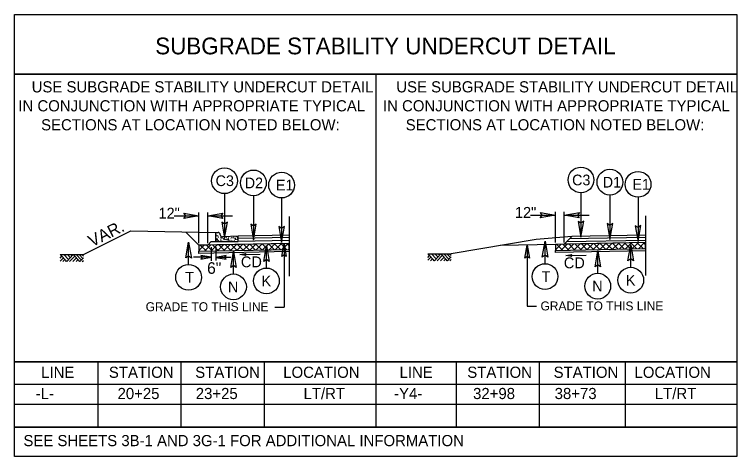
# Model space of a CAD drawing. Extents: x 1904401 to 1905163, y 193929 to 194736.
# Drawn here: x 1904819.8 to 1904900.7, y 193929.1 to 193978.6 of the extents above; entities that cross this region are included whole.
import ezdxf

# ---------------------------------------------------------------- set-up
doc = ezdxf.new("R2010")
doc.units = 0
for name, color, linetype in [('Old_Level_1', 7, 'Continuous'), ('Old_Level_11', 7, 'Continuous'), ('Old_Level_19', 7, 'Continuous'), ('Prop Lane Arrow CELL', 7, 'Continuous'), ('Prop Terminator CELL', 7, 'Continuous'), ('Typical Berm CELL', 7, 'Continuous'), ('Typical Curb CELL', 7, 'Continuous'), ('Typical Detail Wedge1 CELL', 7, 'Continuous'), ('Typical Hinge Slope Arterial CELL', 7, 'Continuous'), ('Typical ID Circle CELL', 7, 'Continuous'), ('Typical Pavement Slope CELL', 7, 'Continuous'), ('Typical Terminator CELL', 7, 'Continuous'), ('Typical Text General CELL', 7, 'Continuous'), ('Typical Text ID Circle CELL', 7, 'Continuous')]:
    doc.layers.add(name, color=color, linetype=linetype)

msp = doc.modelspace()

# ---------------------------------------------------------------- linework, layer by layer
at = {"layer": 'Old_Level_1'}
for p, q in [((1904840.413, 193952.944), (1904840.413, 193956.386)), ((1904841.413, 193952.944), (1904841.413, 193956.386)), ((1904880.325, 193953.027), (1904880.325, 193956.47)), ((1904881.325, 193953.027), (1904881.325, 193956.47)), ((1904837.638, 193956.011), (1904840.413, 193956.011)), ((1904841.413, 193956.011), (1904844.186, 193956.011)), ((1904850.507, 193955.947), (1904850.507, 193949.274)), ((1904877.55, 193956.094), (1904880.325, 193956.094)), ((1904881.325, 193956.094), (1904884.098, 193956.094)), ((1904890.419, 193956.031), (1904890.419, 193949.357)), ((1904850.507, 193953.852), (1904844.804, 193953.738)), ((1904890.419, 193953.852), (1904882.175, 193953.687)), ((1904850.507, 193953.602), (1904844.804, 193953.488)), ((1904850.507, 193953.268), (1904844.804, 193953.154)), ((1904878.175, 193953.367), (1904868.658, 193951.78)), ((1904882.175, 193953.687), (1904878.175, 193953.367)), ((1904890.419, 193953.018), (1904880.325, 193952.816)), ((1904882.175, 193953.687), (1904881.325, 193952.836)), ((1904890.419, 193953.018), (1904881.325, 193952.836)), ((1904890.419, 193953.268), (1904881.58, 193953.091)), ((1904890.419, 193953.602), (1904881.92, 193953.432)), ((1904888.181, 193952.307), (1904888.862, 193952.987)), ((1904888.795, 193952.986), (1904889.449, 193952.332)), ((1904888.903, 193952.321), (1904889.583, 193953.001)), ((1904889.488, 193953), (1904890.142, 193952.346)), ((1904889.625, 193952.335), (1904890.305, 193953.016)), ((1904890.182, 193953.013), (1904890.419, 193952.776)), ((1904890.419, 193952.351), (1904890.419, 193953.018)), ((1904850.507, 193952.935), (1904840.413, 193952.733)), ((1904841.413, 193952.753), (1904840.413, 193952.733)), ((1904840.413, 193952.145), (1904841.013, 193952.745)), ((1904840.413, 193952.733), (1904840.413, 193952.066)), ((1904840.413, 193952.066), (1904850.507, 193952.268)), ((1904840.413, 193952.18), (1904840.525, 193952.068)), ((1904840.564, 193952.736), (1904841.218, 193952.082)), ((1904841.054, 193952.079), (1904841.734, 193952.759)), ((1904841.257, 193952.75), (1904841.911, 193952.096)), ((1904850.507, 193952.935), (1904841.413, 193952.753)), ((1904841.775, 193952.093), (1904842.456, 193952.774)), ((1904841.951, 193952.764), (1904842.604, 193952.11)), ((1904842.497, 193952.108), (1904843.177, 193952.788)), ((1904842.644, 193952.778), (1904843.298, 193952.124)), ((1904843.219, 193952.122), (1904843.899, 193952.803)), ((1904843.337, 193952.791), (1904843.991, 193952.138)), ((1904843.94, 193952.137), (1904844.621, 193952.817)), ((1904844.03, 193952.805), (1904844.684, 193952.152)), ((1904844.662, 193952.151), (1904845.342, 193952.832)), ((1904844.724, 193952.819), (1904845.377, 193952.165)), ((1904845.383, 193952.166), (1904846.064, 193952.846)), ((1904845.417, 193952.833), (1904846.071, 193952.179)), ((1904846.105, 193952.18), (1904846.785, 193952.86)), ((1904846.11, 193952.847), (1904846.764, 193952.193)), ((1904846.803, 193952.861), (1904847.457, 193952.207)), ((1904846.826, 193952.194), (1904847.507, 193952.875)), ((1904847.497, 193952.875), (1904848.15, 193952.221)), ((1904847.548, 193952.209), (1904848.228, 193952.889)), ((1904848.19, 193952.888), (1904848.844, 193952.235)), ((1904848.269, 193952.223), (1904848.95, 193952.904)), ((1904848.883, 193952.902), (1904849.537, 193952.249)), ((1904848.991, 193952.238), (1904849.671, 193952.918)), ((1904849.576, 193952.916), (1904850.23, 193952.262)), ((1904849.712, 193952.252), (1904850.393, 193952.933)), ((1904849.943, 193952.924), (1904849.943, 193945.791)), ((1904850.27, 193952.93), (1904850.507, 193952.692)), ((1904850.434, 193952.267), (1904850.507, 193952.34)), ((1904850.507, 193952.268), (1904850.507, 193952.935)), ((1904880.325, 193952.816), (1904874.129, 193952.692)), ((1904877.173, 193952.753), (1904877.173, 193945.924)), ((1904881.325, 193952.836), (1904880.325, 193952.816)), ((1904880.325, 193952.228), (1904880.925, 193952.828)), ((1904880.325, 193952.816), (1904880.325, 193952.149)), ((1904880.325, 193952.149), (1904890.419, 193952.351)), ((1904880.325, 193952.263), (1904880.437, 193952.152)), ((1904880.476, 193952.819), (1904881.13, 193952.166)), ((1904880.966, 193952.162), (1904881.647, 193952.843)), ((1904881.17, 193952.833), (1904881.823, 193952.179)), ((1904881.688, 193952.177), (1904882.368, 193952.857)), ((1904881.863, 193952.847), (1904882.517, 193952.193)), ((1904882.409, 193952.191), (1904883.09, 193952.872)), ((1904882.556, 193952.861), (1904883.21, 193952.207)), ((1904883.131, 193952.206), (1904883.811, 193952.886)), ((1904883.249, 193952.875), (1904883.903, 193952.221)), ((1904883.852, 193952.22), (1904884.533, 193952.9)), ((1904883.943, 193952.889), (1904884.596, 193952.235)), ((1904884.574, 193952.234), (1904885.254, 193952.915)), ((1904884.636, 193952.903), (1904885.29, 193952.249)), ((1904885.295, 193952.249), (1904885.976, 193952.929)), ((1904885.329, 193952.916), (1904885.983, 193952.263)), ((1904886.017, 193952.263), (1904886.697, 193952.944)), ((1904886.022, 193952.93), (1904886.676, 193952.276)), ((1904886.716, 193952.944), (1904887.369, 193952.29)), ((1904886.738, 193952.278), (1904887.419, 193952.958)), ((1904887.409, 193952.958), (1904888.063, 193952.304)), ((1904887.46, 193952.292), (1904888.14, 193952.973)), ((1904888.102, 193952.972), (1904888.756, 193952.318)), ((1904890.346, 193952.35), (1904890.419, 193952.423)), ((1904824.894, 193951.689), (1904825.617, 193950.91)), ((1904824.894, 193951.288), (1904825.079, 193951.488)), ((1904825.285, 193951.697), (1904825.818, 193951.124)), ((1904825.617, 193950.91), (1904826.349, 193951.696)), ((1904825.683, 193951.697), (1904826.016, 193951.338)), ((1904825.928, 193950.892), (1904826.514, 193951.52)), ((1904826.085, 193951.697), (1904826.218, 193951.554)), ((1904826.349, 193951.696), (1904827.09, 193950.9)), ((1904826.671, 193951.697), (1904827.251, 193951.074)), ((1904827.004, 193951.697), (1904827.418, 193951.253)), ((1904827.324, 193951.697), (1904827.494, 193951.514)), ((1904844.99, 193951.681), (1904847.266, 193951.736)), ((1904866.058, 193951.772), (1904866.782, 193950.993)), ((1904866.058, 193951.371), (1904866.244, 193951.571)), ((1904866.058, 193951.038), (1904866.4, 193951.404)), ((1904866.449, 193951.781), (1904866.982, 193951.207)), ((1904866.782, 193950.993), (1904867.513, 193951.779)), ((1904866.847, 193951.78), (1904867.18, 193951.421)), ((1904867.092, 193950.976), (1904867.678, 193951.604)), ((1904867.249, 193951.78), (1904867.382, 193951.638)), ((1904867.462, 193950.976), (1904867.862, 193951.404)), ((1904867.513, 193951.779), (1904868.254, 193950.984)), ((1904867.835, 193951.781), (1904868.415, 193951.158)), ((1904868.168, 193951.78), (1904868.582, 193951.336)), ((1904868.254, 193950.984), (1904868.658, 193951.419)), ((1904868.488, 193951.781), (1904868.658, 193951.597)), ((1904881.484, 193951.57), (1904883.759, 193951.624)), ((1904824.894, 193950.955), (1904825.236, 193951.321)), ((1904825.182, 193950.892), (1904825.409, 193951.135)), ((1904825.493, 193950.892), (1904825.564, 193950.968)), ((1904826.298, 193950.892), (1904826.698, 193951.321)), ((1904826.664, 193950.892), (1904826.881, 193951.125)), ((1904826.959, 193950.892), (1904827.028, 193950.966)), ((1904827.09, 193950.9), (1904827.494, 193951.335)), ((1904827.36, 193950.892), (1904827.494, 193951.035)), ((1904866.346, 193950.976), (1904866.573, 193951.218)), ((1904866.657, 193950.975), (1904866.728, 193951.051)), ((1904867.828, 193950.976), (1904868.045, 193951.208)), ((1904868.123, 193950.976), (1904868.192, 193951.049)), ((1904868.524, 193950.976), (1904868.658, 193951.119)), ((1904848.917, 193945.791), (1904849.943, 193945.791)), ((1904877.173, 193945.924), (1904878.198, 193945.924))]:
    msp.add_line(p, q, dxfattribs=at)
for points in [[(1904824.894, 193951.697), (1904827.494, 193951.697)], [(1904866.058, 193951.781), (1904868.658, 193951.78)]]:
    msp.add_lwpolyline(points, dxfattribs=at)
at = {"layer": 'Old_Level_11'}
for points in [[(1904849.693, 193951.469), (1904849.943, 193952.924), (1904850.202, 193951.461), (1904849.943, 193951.646)], [(1904876.922, 193951.298), (1904877.173, 193952.753), (1904877.431, 193951.291), (1904877.173, 193951.476)]]:
    msp.add_lwpolyline(points, close=True, dxfattribs=at)
at = {"layer": 'Old_Level_19'}
for p, q in [((1904860.211, 193971.866), (1904860.211, 193932.36)), ((1904860.211, 193969.311), (1904860.211, 193932.36)), ((1904829.079, 193939.673), (1904829.079, 193932.36)), ((1904838.395, 193939.673), (1904838.395, 193932.36)), ((1904847.712, 193939.673), (1904847.712, 193932.36)), ((1904869.208, 193939.673), (1904869.208, 193932.36)), ((1904878.524, 193939.673), (1904878.524, 193932.36)), ((1904888.16, 193939.673), (1904888.16, 193932.36)), ((1904900.659, 193937.118), (1904819.762, 193937.118)), ((1904829.079, 193937.118), (1904829.079, 193932.36)), ((1904838.395, 193937.118), (1904838.395, 193932.36)), ((1904847.712, 193937.118), (1904847.712, 193932.36)), ((1904869.208, 193937.118), (1904869.208, 193932.36)), ((1904878.524, 193937.118), (1904878.524, 193932.36)), ((1904888.16, 193937.118), (1904888.16, 193932.36)), ((1904900.659, 193934.915), (1904819.762, 193934.915)), ((1904900.659, 193932.36), (1904819.762, 193932.36))]:
    msp.add_line(p, q, dxfattribs=at)
for points in [[(1904819.762, 193978.563), (1904900.659, 193978.563), (1904900.659, 193971.866), (1904819.762, 193971.866)], [(1904819.762, 193971.866), (1904900.659, 193971.866), (1904900.659, 193939.673), (1904819.762, 193939.673)], [(1904819.762, 193932.36), (1904900.659, 193932.36), (1904900.659, 193929.071), (1904819.762, 193929.071)]]:
    msp.add_lwpolyline(points, close=True, dxfattribs=at)
msp.add_lwpolyline([(1904819.762, 193929.071), (1904819.762, 193939.673), (1904900.659, 193939.673), (1904900.659, 193929.071)], dxfattribs=at)
at = {"layer": 'Prop Lane Arrow CELL'}
for p, q in [((1904841.804, 193952.504), (1904841.804, 193950.965)), ((1904842.304, 193952.503), (1904842.304, 193951.005)), ((1904841.804, 193951.387), (1904839.814, 193951.387)), ((1904843.976, 193951.359), (1904842.304, 193951.359))]:
    msp.add_line(p, q, dxfattribs=at)
at = {"layer": 'Prop Terminator CELL'}
for points in [[(1904839.963, 193956.088), (1904840.413, 193956.011), (1904839.96, 193955.931), (1904840.018, 193956.011)], [(1904841.863, 193955.933), (1904841.413, 193956.011), (1904841.865, 193956.091), (1904841.808, 193956.011)], [(1904879.875, 193956.172), (1904880.325, 193956.094), (1904879.873, 193956.014), (1904879.93, 193956.094)], [(1904881.775, 193956.017), (1904881.325, 193956.094), (1904881.778, 193956.174), (1904881.72, 193956.094)], [(1904845.668, 193951.581), (1904844.99, 193951.681), (1904845.666, 193951.817), (1904845.582, 193951.695)], [(1904882.161, 193951.47), (1904881.484, 193951.57), (1904882.159, 193951.706), (1904882.076, 193951.584)]]:
    msp.add_lwpolyline(points, close=True, dxfattribs=at)
at = {"layer": 'Typical Berm CELL'}
msp.add_line((1904832.804, 193954.352), (1904842.304, 193954.154), dxfattribs=at)
at = {"layer": 'Typical Curb CELL'}
for p, q in [((1904842.304, 193953.154), (1904842.304, 193954.154)), ((1904842.304, 193954.154), (1904842.564, 193954.154)), ((1904842.341, 193953.776), (1904842.495, 193953.821)), ((1904842.495, 193953.821), (1904842.478, 193953.73)), ((1904842.804, 193953.904), (1904842.804, 193953.915)), ((1904842.304, 193953.154), (1904844.804, 193953.154)), ((1904842.478, 193953.73), (1904842.341, 193953.776)), ((1904842.467, 193953.457), (1904842.363, 193953.382)), ((1904842.363, 193953.382), (1904842.529, 193953.343)), ((1904842.529, 193953.343), (1904842.467, 193953.457)), ((1904844.804, 193953.738), (1904843.054, 193953.665)), ((1904843.208, 193953.514), (1904843.174, 193953.4)), ((1904843.174, 193953.4), (1904843.294, 193953.394)), ((1904843.294, 193953.394), (1904843.208, 193953.514)), ((1904843.715, 193953.457), (1904843.612, 193953.382)), ((1904843.612, 193953.382), (1904843.778, 193953.343)), ((1904843.778, 193953.343), (1904843.715, 193953.457)), ((1904844.457, 193953.514), (1904844.423, 193953.4)), ((1904844.423, 193953.4), (1904844.543, 193953.394)), ((1904844.543, 193953.394), (1904844.457, 193953.514)), ((1904844.804, 193953.154), (1904844.804, 193953.738))]:
    msp.add_line(p, q, dxfattribs=at)
for centre in [(1904842.317, 193954.044), (1904842.369, 193953.861), (1904842.534, 193954.078), (1904842.449, 193953.2), (1904842.466, 193953.588), (1904842.586, 193953.639), (1904842.62, 193953.24), (1904842.763, 193953.474), (1904842.797, 193953.177), (1904842.843, 193953.667), (1904842.854, 193953.292), (1904842.86, 193953.617), (1904842.888, 193953.446), (1904842.968, 193953.206), (1904843.037, 193953.531), (1904843.065, 193953.633), (1904843.174, 193953.229), (1904843.26, 193953.594), (1904843.334, 193953.16), (1904843.356, 193953.648), (1904843.385, 193953.394), (1904843.465, 193953.554), (1904843.481, 193953.349), (1904843.521, 193953.588), (1904843.538, 193953.491), (1904843.544, 193953.183), (1904843.698, 193953.2), (1904843.715, 193953.588), (1904843.835, 193953.639), (1904843.869, 193953.24), (1904844.012, 193953.474), (1904844.046, 193953.177), (1904844.092, 193953.667), (1904844.103, 193953.292), (1904844.109, 193953.617), (1904844.137, 193953.446), (1904844.217, 193953.206), (1904844.286, 193953.531), (1904844.314, 193953.633), (1904844.423, 193953.229), (1904844.463, 193953.696), (1904844.509, 193953.594), (1904844.583, 193953.16), (1904844.606, 193953.679), (1904844.634, 193953.394), (1904844.714, 193953.554), (1904844.73, 193953.349), (1904844.77, 193953.588), (1904844.787, 193953.491), (1904844.793, 193953.183)]:
    msp.add_circle(centre, 0.00802, dxfattribs=at)
for centre, start, end in [((1904842.564, 193953.915), 0, 90), ((1904843.044, 193953.904), 180, 272.38446)]:
    msp.add_arc(centre, 0.24, start, end, dxfattribs=at)
at = {"layer": 'Typical Detail Wedge1 CELL'}
for points in [[(1904840.413, 193952.066), (1904850.507, 193952.268), (1904850.507, 193952.018), (1904840.413, 193951.816)], [(1904880.325, 193952.149), (1904890.419, 193952.351), (1904890.419, 193952.101), (1904880.325, 193951.899)]]:
    msp.add_lwpolyline(points, close=True, dxfattribs=at)
at = {"layer": 'Typical Hinge Slope Arterial CELL'}
msp.add_line((1904827.494, 193951.697), (1904832.804, 193954.352), dxfattribs=at)
at = {"layer": 'Typical ID Circle CELL'}
for p, q in [((1904843.282, 193958.508), (1904843.282, 193953.537)), ((1904846.52, 193958.258), (1904846.52, 193953.287)), ((1904849.675, 193958.019), (1904849.675, 193953.048)), ((1904883.194, 193958.591), (1904883.194, 193953.621)), ((1904886.432, 193958.341), (1904886.432, 193953.37)), ((1904889.587, 193958.102), (1904889.587, 193953.132)), ((1904839.257, 193950.576), (1904839.257, 193953.085)), ((1904879.17, 193950.659), (1904879.17, 193953.169)), ((1904847.975, 193950.17), (1904847.975, 193952.68)), ((1904888.764, 193950.254), (1904888.764, 193952.763)), ((1904844.283, 193949.507), (1904844.283, 193952.016)), ((1904885.072, 193949.59), (1904885.072, 193952.1))]:
    msp.add_line(p, q, dxfattribs=at)
for centre in [(1904843.282, 193959.951), (1904846.52, 193959.701), (1904883.194, 193960.034), (1904886.432, 193959.784), (1904849.675, 193959.462), (1904889.587, 193959.545), (1904839.257, 193949.133), (1904879.17, 193949.217), (1904847.975, 193948.728), (1904888.764, 193948.811), (1904844.283, 193948.065), (1904885.072, 193948.148)]:
    msp.add_circle(centre, 1.443, dxfattribs=at)
at = {"layer": 'Typical Pavement Slope CELL'}
for p, q in [((1904840.413, 193952.733), (1904838.963, 193954.183)), ((1904841.413, 193952.753), (1904841.804, 193953.144)), ((1904841.804, 193953.144), (1904842.304, 193953.154))]:
    msp.add_line(p, q, dxfattribs=at)
at = {"layer": 'Typical Terminator CELL'}
for points in [[(1904838.734, 193956.3), (1904840.413, 193956.011), (1904838.725, 193955.712), (1904838.94, 193956.011)], [(1904843.091, 193955.722), (1904841.413, 193956.011), (1904843.101, 193956.309), (1904842.886, 193956.011)], [(1904878.647, 193956.383), (1904880.325, 193956.094), (1904878.637, 193955.796), (1904878.852, 193956.094)], [(1904883.004, 193955.805), (1904881.325, 193956.094), (1904883.013, 193956.392), (1904882.798, 193956.094)], [(1904882.887, 193955.402), (1904883.194, 193953.621), (1904883.511, 193955.411), (1904883.194, 193955.184)], [(1904842.975, 193955.318), (1904843.282, 193953.537), (1904843.598, 193955.328), (1904843.282, 193955.1)], [(1904846.213, 193955.068), (1904846.52, 193953.287), (1904846.836, 193955.078), (1904846.52, 193954.85)], [(1904849.368, 193954.829), (1904849.675, 193953.048), (1904849.991, 193954.839), (1904849.675, 193954.611)], [(1904886.125, 193955.151), (1904886.432, 193953.37), (1904886.749, 193955.161), (1904886.432, 193954.934)], [(1904889.28, 193954.912), (1904889.587, 193953.132), (1904889.904, 193954.922), (1904889.587, 193954.695)], [(1904838.951, 193951.304), (1904839.257, 193953.085), (1904839.574, 193951.294), (1904839.257, 193951.522)], [(1904878.863, 193951.388), (1904879.17, 193953.169), (1904879.486, 193951.378), (1904879.17, 193951.605)], [(1904847.669, 193950.899), (1904847.975, 193952.68), (1904848.292, 193950.889), (1904847.975, 193951.116)], [(1904888.457, 193950.982), (1904888.764, 193952.763), (1904889.08, 193950.972), (1904888.764, 193951.2)], [(1904840.633, 193951.185), (1904841.804, 193951.387), (1904840.626, 193951.595), (1904840.776, 193951.387)], [(1904843.476, 193951.561), (1904842.304, 193951.359), (1904843.482, 193951.151), (1904843.333, 193951.359)], [(1904843.977, 193950.235), (1904844.283, 193952.016), (1904844.6, 193950.225), (1904844.283, 193950.453)], [(1904884.765, 193950.319), (1904885.072, 193952.1), (1904885.389, 193950.309), (1904885.072, 193950.536)]]:
    msp.add_lwpolyline(points, close=True, dxfattribs=at)

# ---------------------------------------------------------------- texts
at = {"layer": 'Old_Level_1'}
for s, height, p in [('12"', 1.2169, (1904875.8, 193955.793)), ('12"', 1.2169, (1904835.888, 193955.71)), ('CD', 1.2169, (1904845.117, 193950.257)), ('CD', 1.2169, (1904881.275, 193950.145)), ('6" ', 1.3, (1904841.334, 193949.523))]:
    msp.add_text(s, height=height, dxfattribs=at).set_placement(p)
at = {"layer": 'Old_Level_11'}
for s, height, p in [('SUBGRADE STABILITY UNDERCUT DETAIL', 1.875, (1904835.523, 193974.098)), ('USE SUBGRADE STABILITY UNDERCUT DETAIL ', 1.25, (1904821.689, 193969.837)), ('USE SUBGRADE STABILITY UNDERCUT DETAIL ', 1.25, (1904862.514, 193969.837)), ('IN CONJUNCTION WITH APPROPRIATE TYPICAL ', 1.25, (1904820.2, 193967.712)), ('IN CONJUNCTION WITH APPROPRIATE TYPICAL ', 1.25, (1904861.024, 193967.712)), ('SECTIONS AT LOCATION NOTED BELOW:', 1.25, (1904822.747, 193965.587)), ('SECTIONS AT LOCATION NOTED BELOW:', 1.25, (1904863.571, 193965.587)), ('LINE', 1.25, (1904822.754, 193937.881)), ('STATION', 1.25, (1904830.336, 193937.881)), ('STATION', 1.25, (1904840.004, 193937.881)), ('LOCATION', 1.25, (1904849.857, 193937.881)), ('LINE', 1.25, (1904862.884, 193937.881)), ('STATION', 1.25, (1904870.465, 193937.881)), ('STATION', 1.25, (1904880.133, 193937.881)), ('LOCATION', 1.25, (1904889.188, 193937.881)), ('LT/RT', 1.25, (1904852.132, 193935.503)), ('LT/RT', 1.25, (1904891.464, 193935.503)), ('-L-', 1.25, (1904822.142, 193935.503)), ('20+25', 1.25, (1904831.305, 193935.503)), ('23+25', 1.25, (1904840.065, 193935.503)), ('-Y4-', 1.25, (1904862.271, 193935.503)), ('32+98', 1.25, (1904871.112, 193935.503)), ('38+73', 1.25, (1904880.248, 193935.503)), ('SEE SHEETS 3B-1 AND 3G-1 FOR ADDITIONAL INFORMATION', 1.25, (1904820.768, 193930.231))]:
    msp.add_text(s, height=height, dxfattribs=at).set_placement(p)
at = {"layer": 'Typical Hinge Slope Arterial CELL'}
msp.add_text('VAR.', height=1.35, rotation=26.56505, dxfattribs=at).set_placement((1904828.437, 193952.496))
at = {"layer": 'Typical Text General CELL'}
for p in [(1904834.458, 193945.345), (1904878.667, 193945.429)]:
    msp.add_text('GRADE TO THIS LINE', height=1, dxfattribs=at).set_placement(p)
at = {"layer": 'Typical Text ID Circle CELL'}
for s, p in [('C3', (1904842.286, 193959.351)), ('D2', (1904845.546, 193959.101)), ('C3', (1904882.199, 193959.434)), ('D1', (1904885.63, 193959.184)), ('E1', (1904849.038, 193958.862)), ('E1', (1904888.95, 193958.945))]:
    msp.add_text(s, height=1.2, dxfattribs=at).set_placement(p)
for s, p in [('T', (1904878.786, 193948.617)), ('T', (1904838.874, 193948.533)), ('K', (1904847.432, 193948.128)), ('K', (1904888.22, 193948.211)), ('N', (1904843.669, 193947.465)), ('N', (1904884.458, 193947.548))]:
    msp.add_text(s, height=1.2, rotation=360, dxfattribs=at).set_placement(p)

doc.saveas('drawing.dxf')
